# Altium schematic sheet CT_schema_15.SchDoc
size 668 x 614 mm
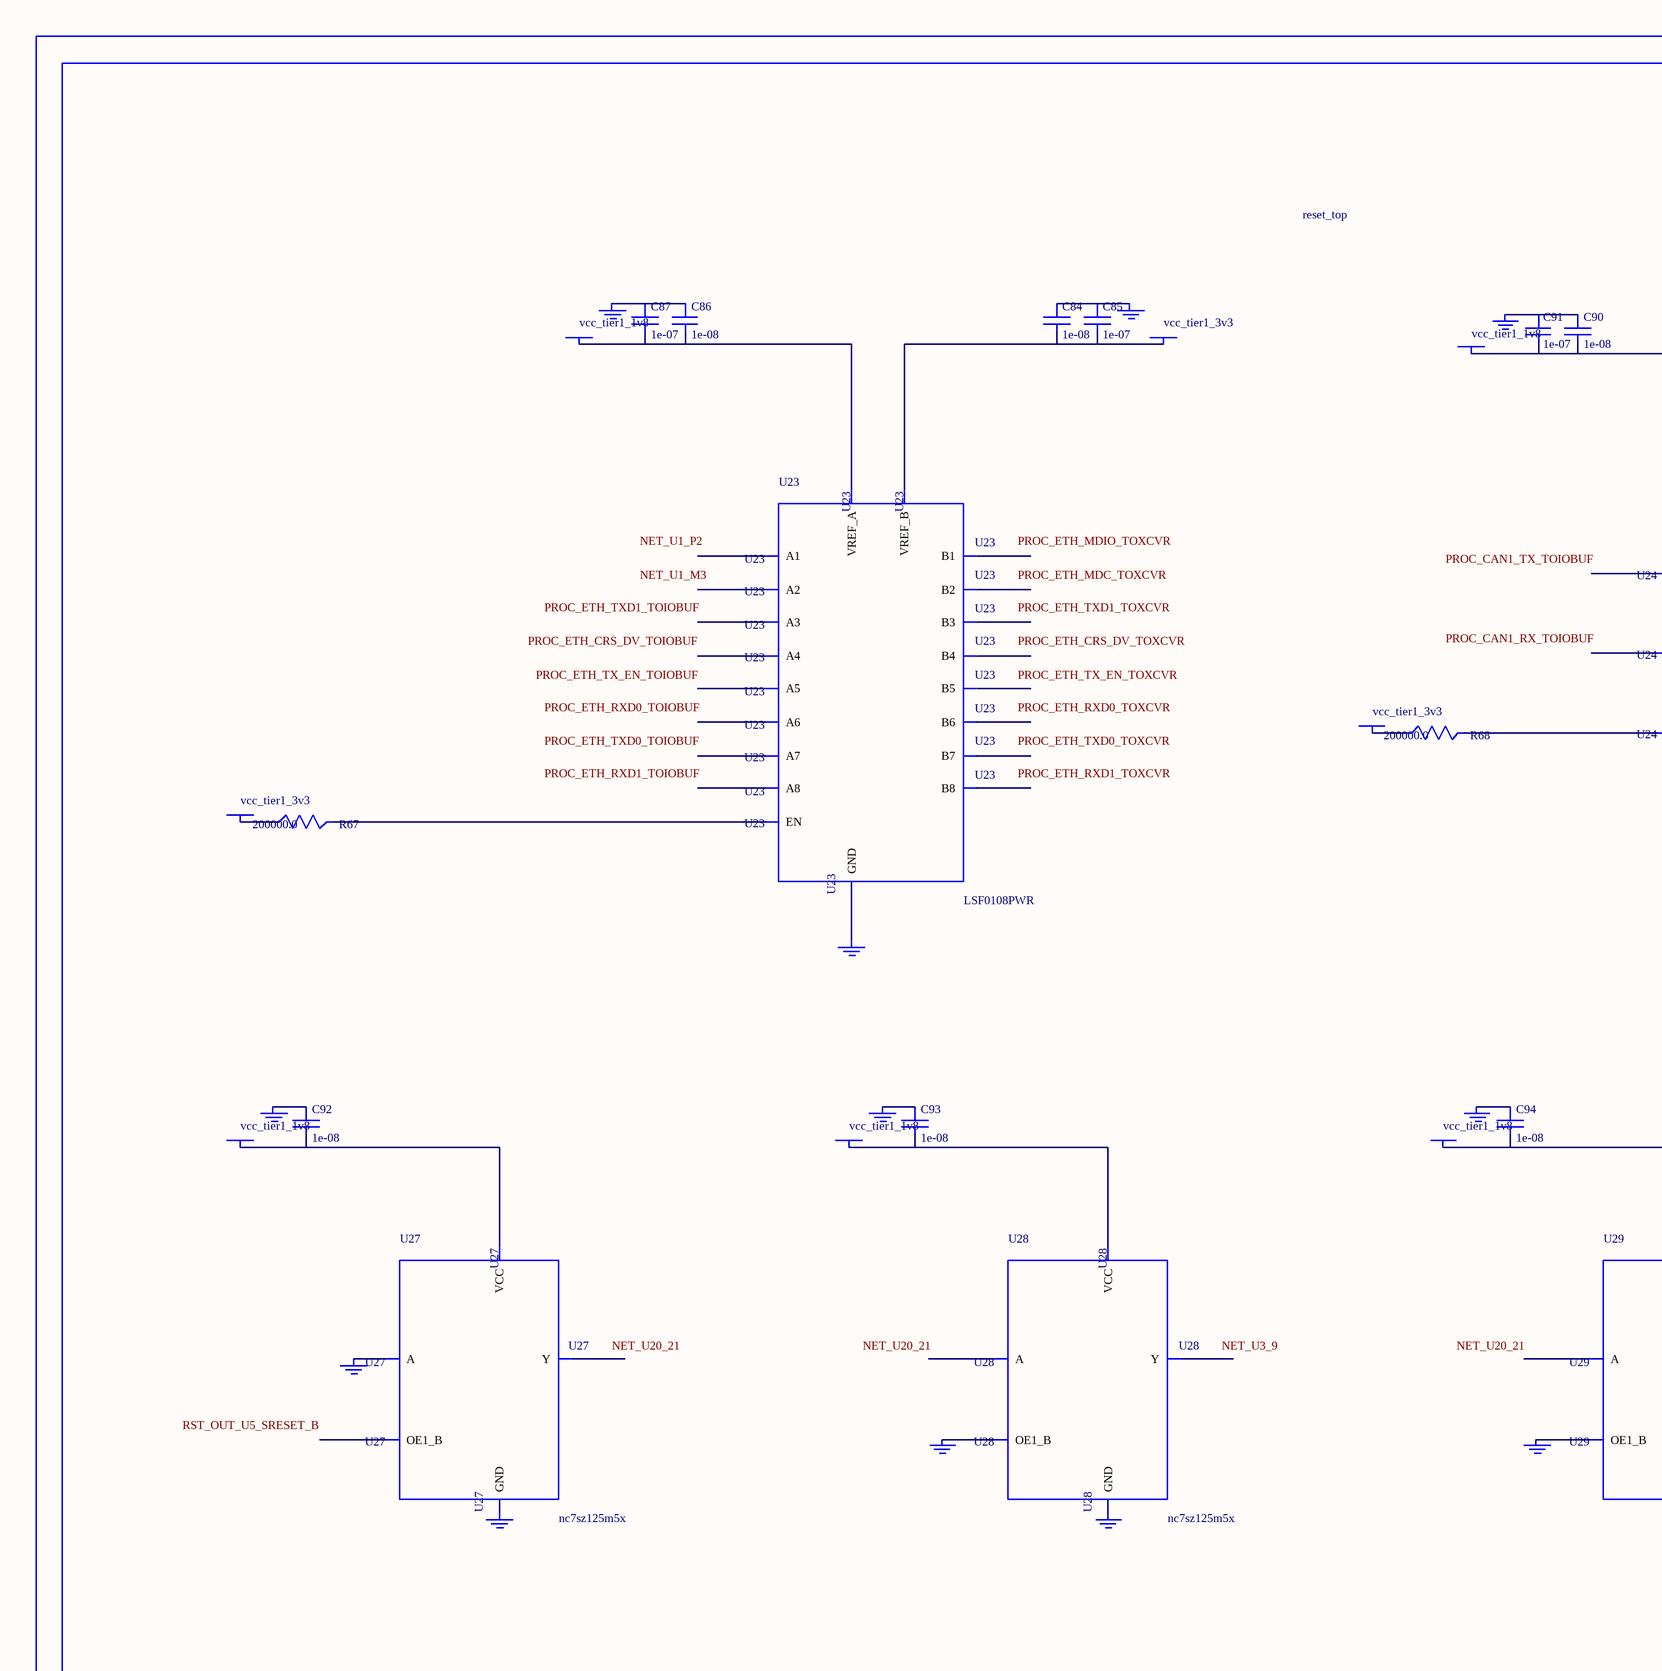
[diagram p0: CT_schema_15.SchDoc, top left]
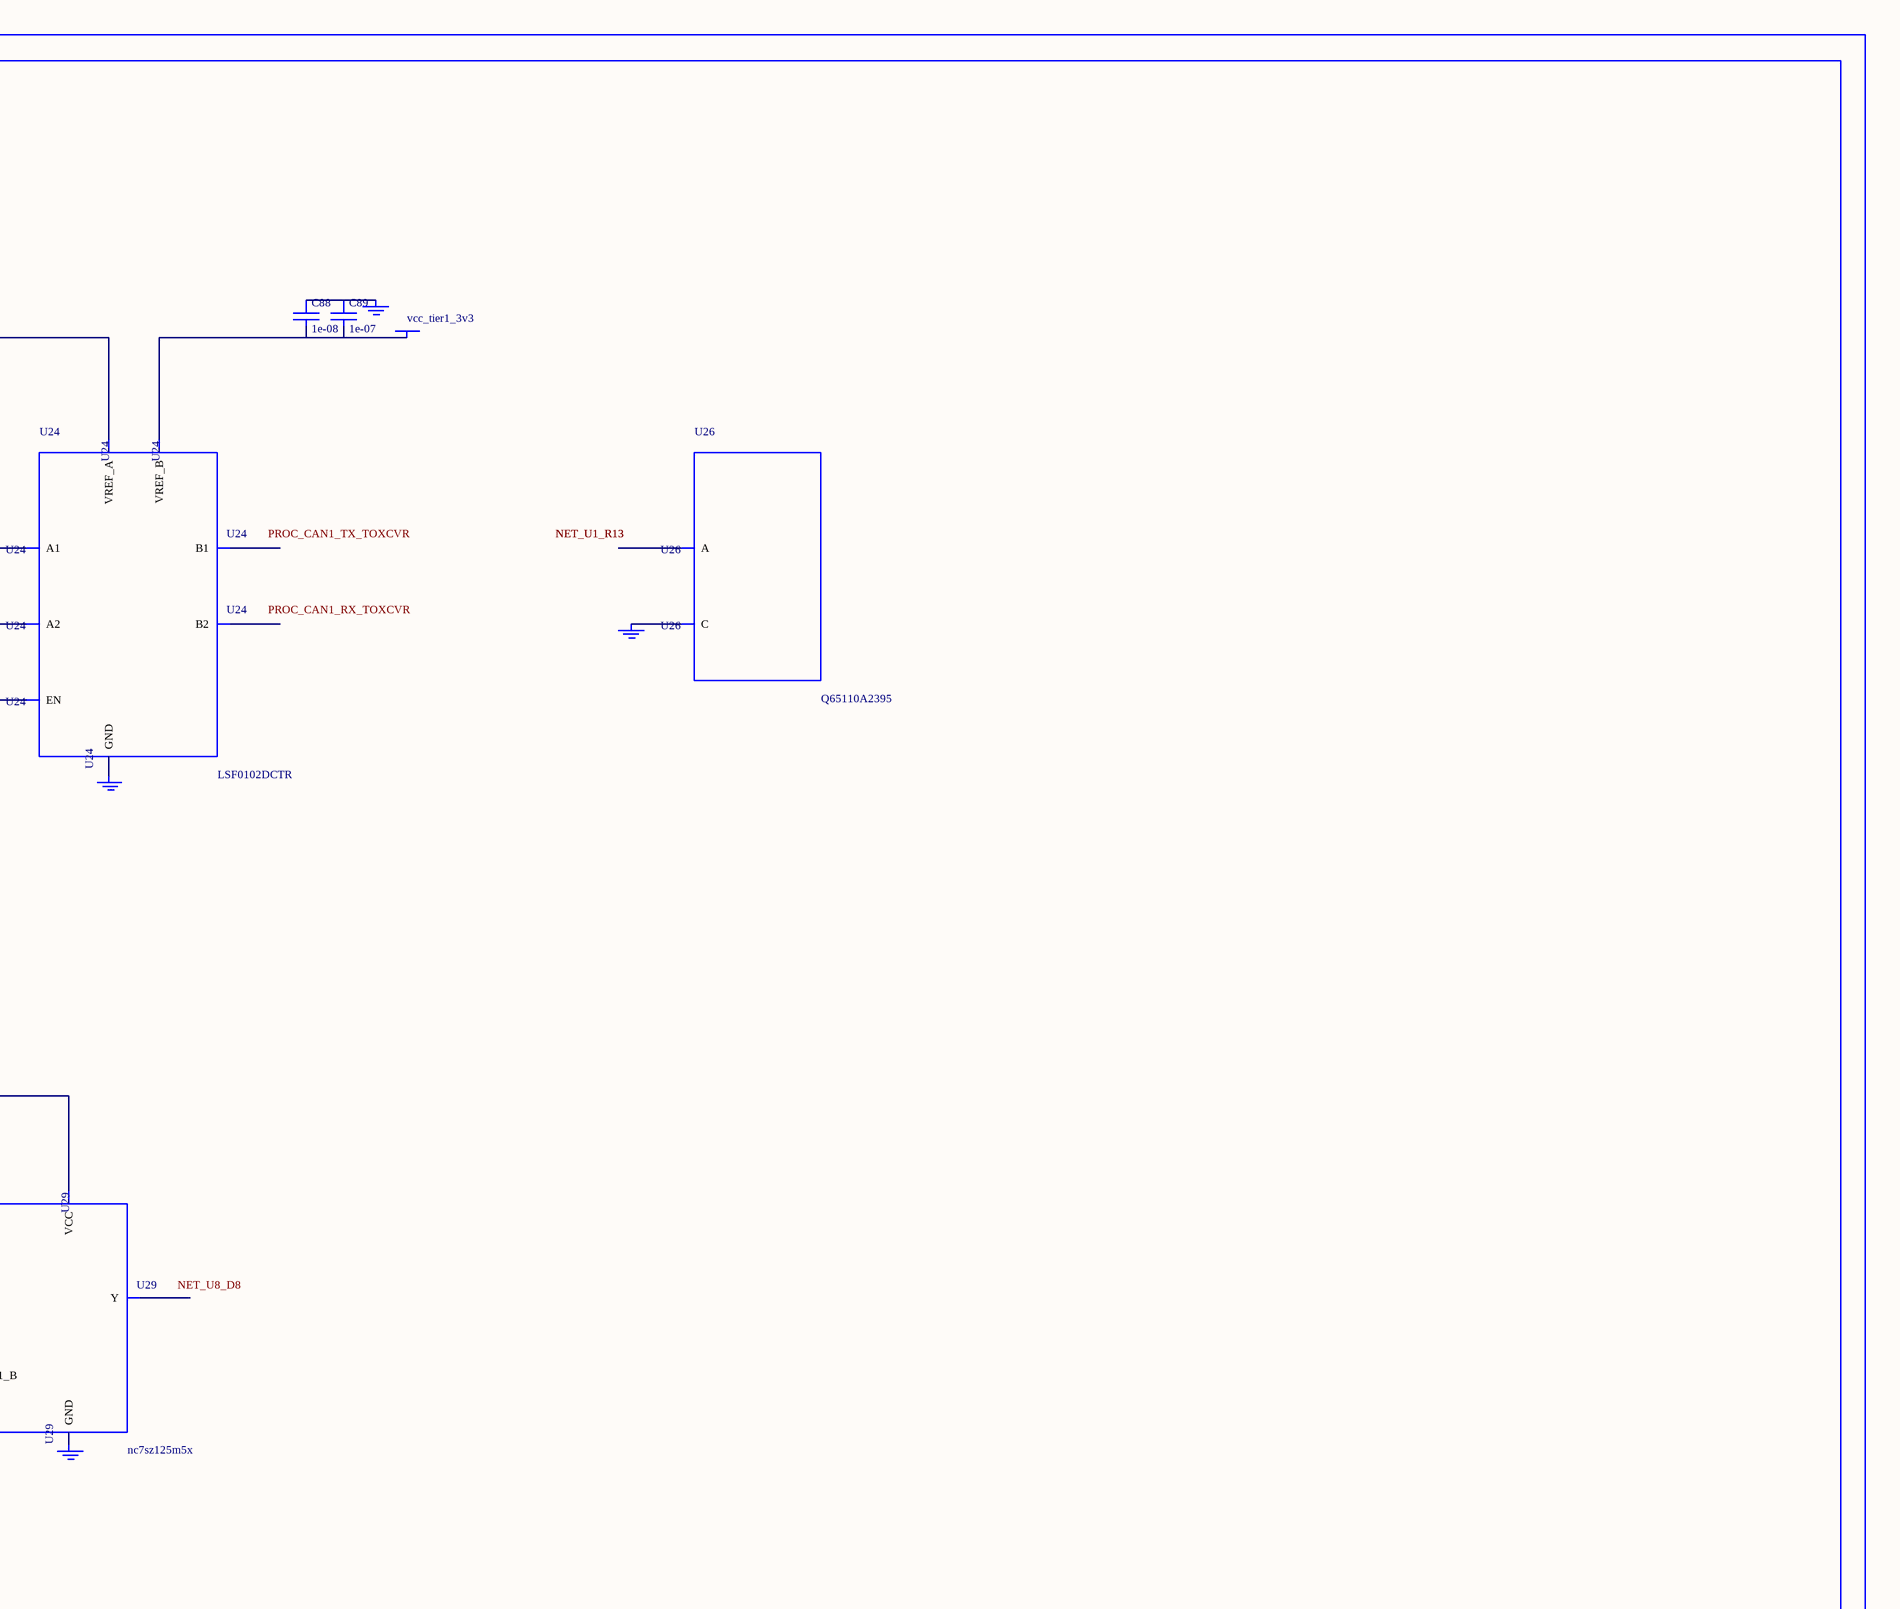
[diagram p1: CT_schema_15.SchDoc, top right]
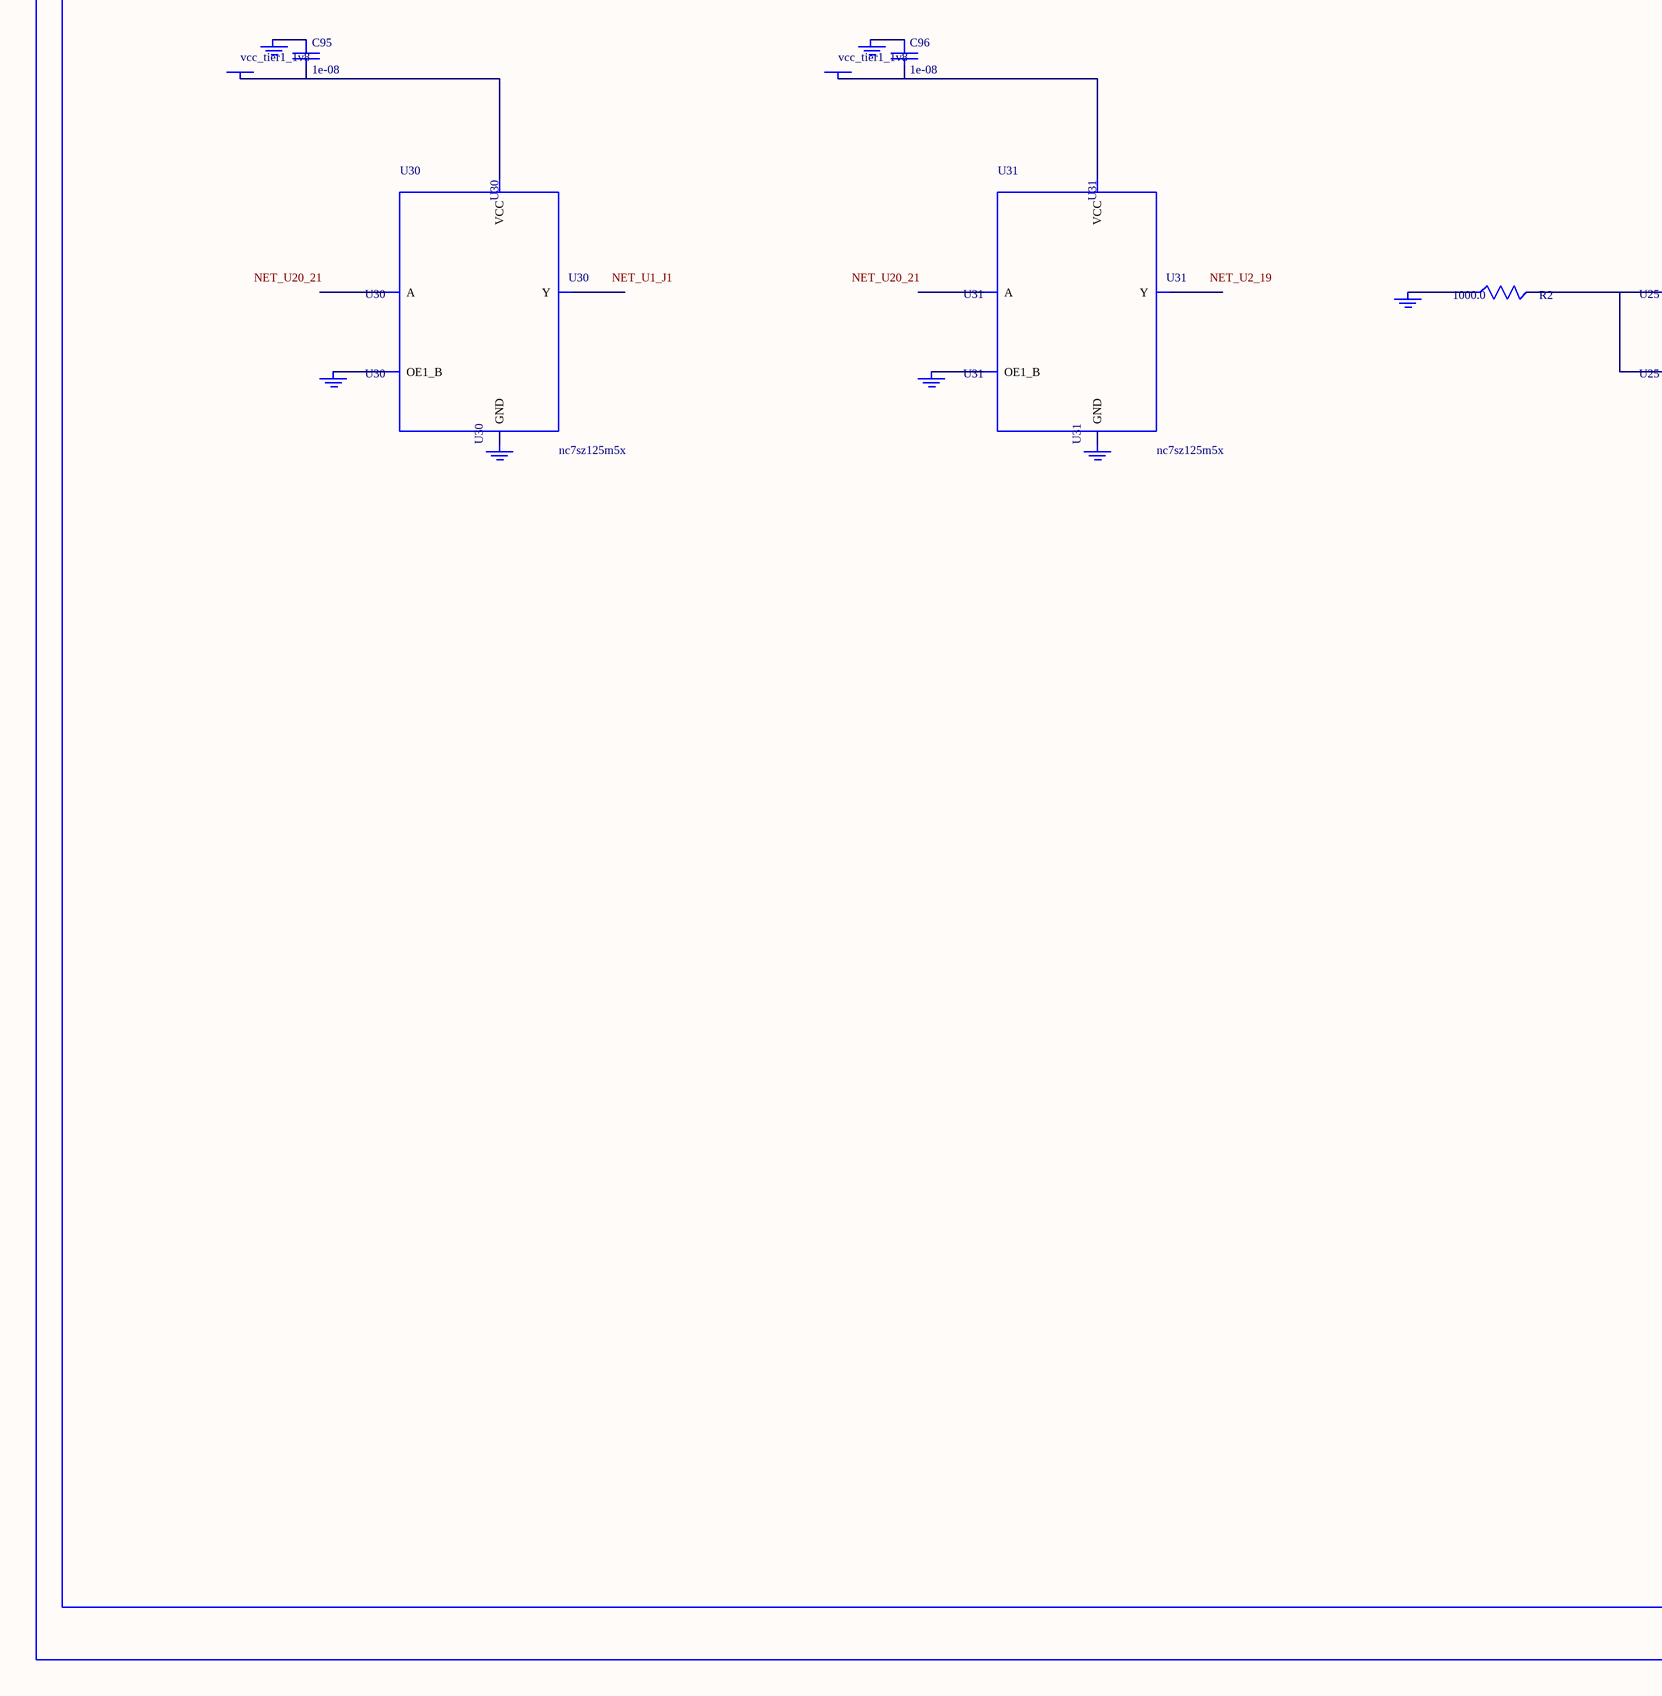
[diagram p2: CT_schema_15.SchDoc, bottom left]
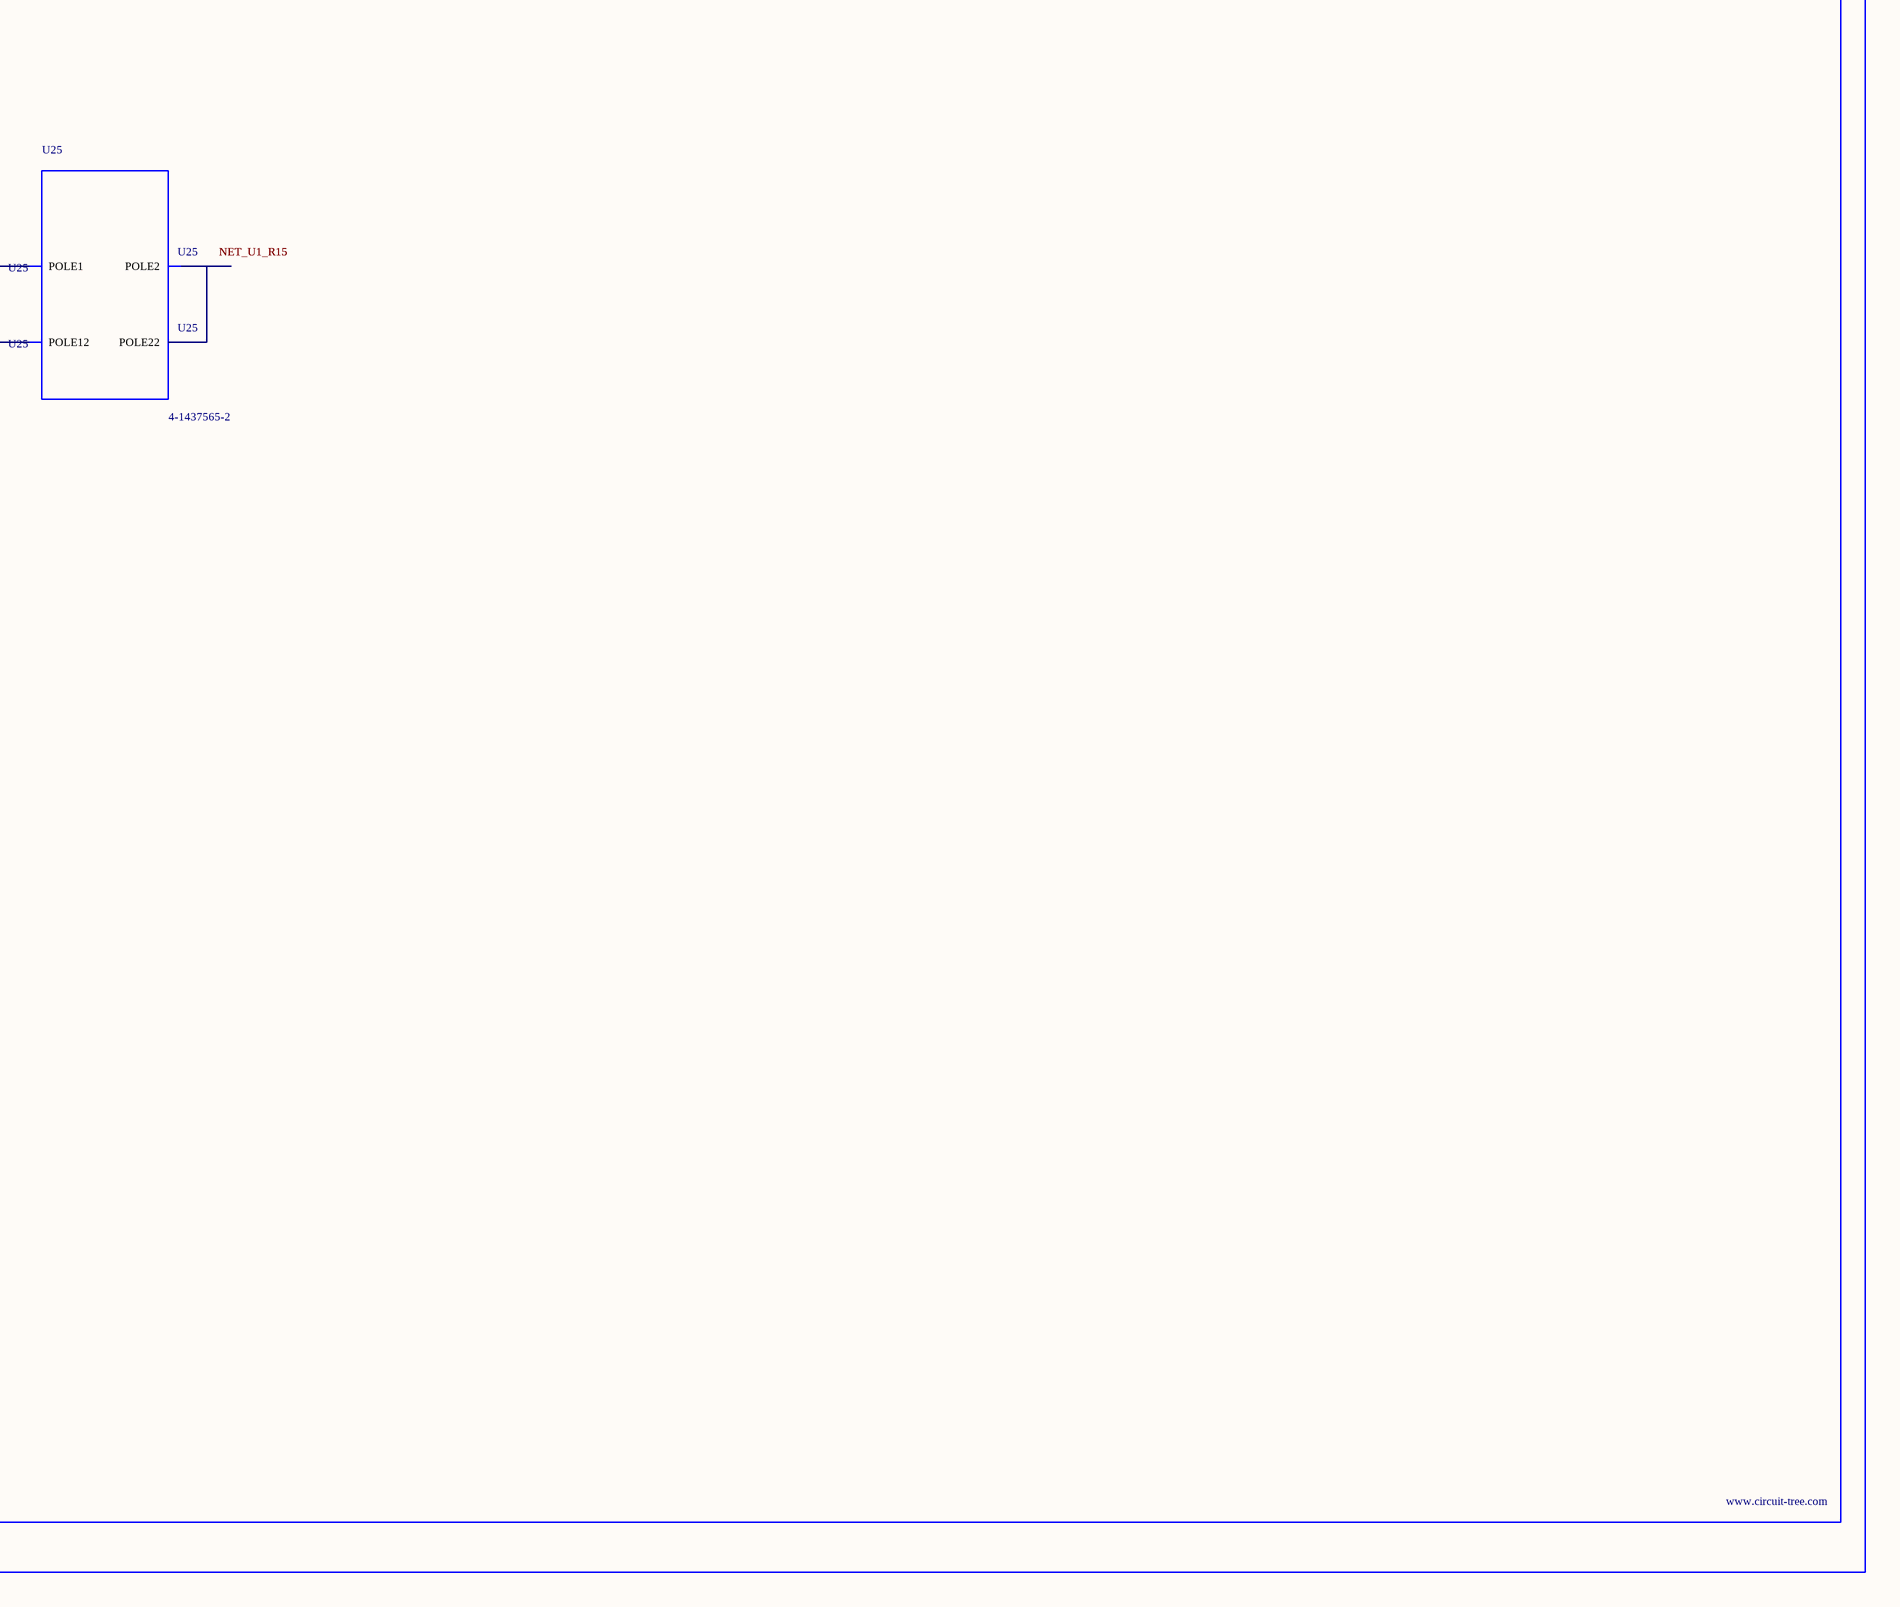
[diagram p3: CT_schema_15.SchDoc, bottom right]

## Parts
BORDER14  (no value)
C84  1e-08  [C0402]
C85  1e-07  [C0402]
C86  1e-08  [C0402]
C87  1e-07  [C0402]
C88  1e-08  [C0402]
C89  1e-07  [C0402]
C90  1e-08  [C0402]
C91  1e-07  [C0402]
C92  1e-08  [C0402]
C93  1e-08  [C0402]
C94  1e-08  [C0402]
C95  1e-08  [C0402]
C96  1e-08  [C0402]
GND_INSTANCE_14_0  (no value)
GND_INSTANCE_14_1  (no value)
GND_INSTANCE_14_2  (no value)
GND_INSTANCE_14_3  (no value)
GND_INSTANCE_14_4  (no value)
GND_INSTANCE_14_5  (no value)
GND_INSTANCE_14_6  (no value)
GND_INSTANCE_14_7  (no value)
GND_INSTANCE_14_8  (no value)
GND_INSTANCE_14_9  (no value)
GND_INSTANCE_14_10  (no value)
GND_INSTANCE_14_11  (no value)
GND_INSTANCE_14_12  (no value)
GND_INSTANCE_14_13  (no value)
GND_INSTANCE_14_14  (no value)
GND_INSTANCE_14_15  (no value)
GND_INSTANCE_14_16  (no value)
GND_INSTANCE_14_17  (no value)
GND_INSTANCE_14_18  (no value)
GND_INSTANCE_14_19  (no value)
GND_INSTANCE_14_20  (no value)
GND_INSTANCE_14_21  (no value)
GND_INSTANCE_14_22  (no value)
POWER_INSTANCE_14_0  vcc_tier1_1v8
POWER_INSTANCE_14_1  vcc_tier1_3v3
POWER_INSTANCE_14_2  vcc_tier1_3v3
POWER_INSTANCE_14_3  vcc_tier1_1v8
POWER_INSTANCE_14_4  vcc_tier1_3v3
POWER_INSTANCE_14_5  vcc_tier1_3v3
POWER_INSTANCE_14_6  vcc_tier1_1v8
POWER_INSTANCE_14_7  vcc_tier1_1v8
POWER_INSTANCE_14_8  vcc_tier1_1v8
POWER_INSTANCE_14_9  vcc_tier1_1v8
POWER_INSTANCE_14_10  vcc_tier1_1v8
R2  1000.0  [R0603]
R67  200000.0  [R0603]
R68  200000.0  [R0603]
U23  LSF0108PWR  [PW0020A]
U24  LSF0102DCTR  [DCU0008A_N]
U25  4-1437565-2  [SW_4-1437565-2]
U26  Q65110A2395  [LGM67K-G1J2-24-Z]
U27  nc7sz125m5x  [NC7SZ125M5X]
U28  nc7sz125m5x  [NC7SZ125M5X]
U29  nc7sz125m5x  [NC7SZ125M5X]
U30  nc7sz125m5x  [NC7SZ125M5X]
U31  nc7sz125m5x  [NC7SZ125M5X]

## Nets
NetC84_1: C84.1 C85.1 GND_INSTANCE_14_1.0(GND)
NetC84_2: C84.2 C85.2 POWER_INSTANCE_14_1.0(PWR) U23.19(VREF_B)
NetC86_1: C86.1 C87.1 GND_INSTANCE_14_0.0(GND)
NetC86_2: C86.2 C87.2 POWER_INSTANCE_14_0.0(PWR) U23.2(VREF_A)
NetC88_1: C88.1 C89.1 GND_INSTANCE_14_4.0(GND)
NetC88_2: C88.2 C89.2 POWER_INSTANCE_14_4.0(PWR) U24.7(VREF_B)
NetC90_1: C90.1 C91.1 GND_INSTANCE_14_3.0(GND)
NetC90_2: C90.2 C91.2 POWER_INSTANCE_14_3.0(PWR) U24.2(VREF_A)
NetC92_1: C92.1 GND_INSTANCE_14_8.0(GND)
NetC92_2: C92.2 POWER_INSTANCE_14_6.0(PWR) U27.5(VCC)
NetC93_1: C93.1 GND_INSTANCE_14_11.0(GND)
NetC93_2: C93.2 POWER_INSTANCE_14_7.0(PWR) U28.5(VCC)
NetC94_1: C94.1 GND_INSTANCE_14_14.0(GND)
NetC94_2: C94.2 POWER_INSTANCE_14_8.0(PWR) U29.5(VCC)
NetC95_1: C95.1 GND_INSTANCE_14_17.0(GND)
NetC95_2: C95.2 POWER_INSTANCE_14_9.0(PWR) U30.5(VCC)
NetC96_1: C96.1 GND_INSTANCE_14_20.0(GND)
NetC96_2: C96.2 POWER_INSTANCE_14_10.0(PWR) U31.5(VCC)
NetGND_INSTANCE_14_2_0: GND_INSTANCE_14_2.0(GND) U23.1(GND)
NetGND_INSTANCE_14_5_0: GND_INSTANCE_14_5.0(GND) U24.1(GND)
NetGND_INSTANCE_14_6_0: GND_INSTANCE_14_6.0(GND) R2.1
NetGND_INSTANCE_14_7_0: GND_INSTANCE_14_7.0(GND) U26.C
NetGND_INSTANCE_14_9_0: GND_INSTANCE_14_9.0(GND) U27.2(A)
NetGND_INSTANCE_14_10_0: GND_INSTANCE_14_10.0(GND) U27.3(GND)
NetGND_INSTANCE_14_12_0: GND_INSTANCE_14_12.0(GND) U28.1(OE1_B)
NetGND_INSTANCE_14_13_0: GND_INSTANCE_14_13.0(GND) U28.3(GND)
NetGND_INSTANCE_14_15_0: GND_INSTANCE_14_15.0(GND) U29.1(OE1_B)
NetGND_INSTANCE_14_16_0: GND_INSTANCE_14_16.0(GND) U29.3(GND)
NetGND_INSTANCE_14_18_0: GND_INSTANCE_14_18.0(GND) U30.1(OE1_B)
NetGND_INSTANCE_14_19_0: GND_INSTANCE_14_19.0(GND) U30.3(GND)
NetGND_INSTANCE_14_21_0: GND_INSTANCE_14_21.0(GND) U31.1(OE1_B)
NetGND_INSTANCE_14_22_0: GND_INSTANCE_14_22.0(GND) U31.3(GND)
NetPOWER_INSTANCE_14_2_0: POWER_INSTANCE_14_2.0(PWR) R67.1
NetPOWER_INSTANCE_14_5_0: POWER_INSTANCE_14_5.0(PWR) R68.1
NetR2_2: R2.2 U25.1(POLE1) U25.2(POLE12)
NetR67_2: R67.2 U23.20(EN)
NetR68_2: R68.2 U24.8(EN)
NetU25_3: U25.3(POLE2) U25.4(POLE22)

Not connected (* = marked no-connect by the designer): U23 3(A1) 4(A2) 5(A3) 6(A4) 7(A5) 8(A6) 9(A7) 10(A8) 11(B8) 12(B7) 13(B6) 14(B5) 15(B4) 16(B3) 17(B2) 18(B1); U24 3(A1) 4(A2) 5(B2) 6(B1); U26 A; U27 1(OE1_B) 4(Y); U28 2(A) 4(Y); U29 2(A) 4(Y); U30 2(A) 4(Y); U31 2(A) 4(Y)

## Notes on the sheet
- Labels drawn without touching a wire or pin: NET_U1_J1, NET_U1_M3, NET_U1_P2, NET_U2_19, NET_U3_9, NET_U8_D8, NET_U20_21, PROC_CAN1_RX_TOIOBUF, PROC_CAN1_RX_TOXCVR, PROC_CAN1_TX_TOIOBUF, PROC_CAN1_TX_TOXCVR, PROC_ETH_CRS_DV_TOIOBUF, PROC_ETH_CRS_DV_TOXCVR, PROC_ETH_MDC_TOXCVR, PROC_ETH_MDIO_TOXCVR, PROC_ETH_RXD0_TOIOBUF, PROC_ETH_RXD0_TOXCVR, PROC_ETH_RXD1_TOIOBUF, PROC_ETH_RXD1_TOXCVR, PROC_ETH_TX_EN_TOIOBUF, PROC_ETH_TX_EN_TOXCVR, PROC_ETH_TXD0_TOIOBUF, PROC_ETH_TXD0_TOXCVR, PROC_ETH_TXD1_TOIOBUF, PROC_ETH_TXD1_TOXCVR, RST_OUT_U5_SRESET_B

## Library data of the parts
BORDER14 = BORDER_PAGE14
C84 C86 C88 C90 C92-C96 = C0402C103K3RAC
C85 C87 C89 C91 = C0402C104K3RACTU
GND_INSTANCE_14_0-GND_INSTANCE_14_22 = GND
POWER_INSTANCE_14_0-POWER_INSTANCE_14_10 = PWR
R2 = RC0603JR-071KL
R67 R68 = RC0603JR-07200KL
